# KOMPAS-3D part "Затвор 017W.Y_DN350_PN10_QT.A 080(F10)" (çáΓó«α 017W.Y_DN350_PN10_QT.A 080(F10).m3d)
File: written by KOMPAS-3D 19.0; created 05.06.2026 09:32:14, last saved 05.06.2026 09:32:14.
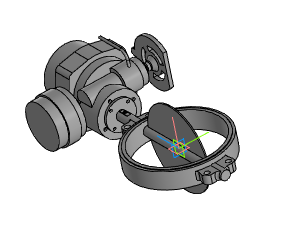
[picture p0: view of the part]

Document properties: Автор: Энергия; Полное имя файла: ..\..\..\3d для проектировщиков\x.x Тип 017W.Y(S) Затвор дисковый поворотный межфланцевый\Затвор 017W.Y(S)_DN32-DN1200_QT.A_MT903.A\Затвор 017W.Y_DN350_PN10_QT.A 080(F10).a3d

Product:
- Part/product: Затвор 017W.Y_DN350_PN10_QT.A 080(F10)
    Масса: 167.701

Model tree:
1. Операция без истории:1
